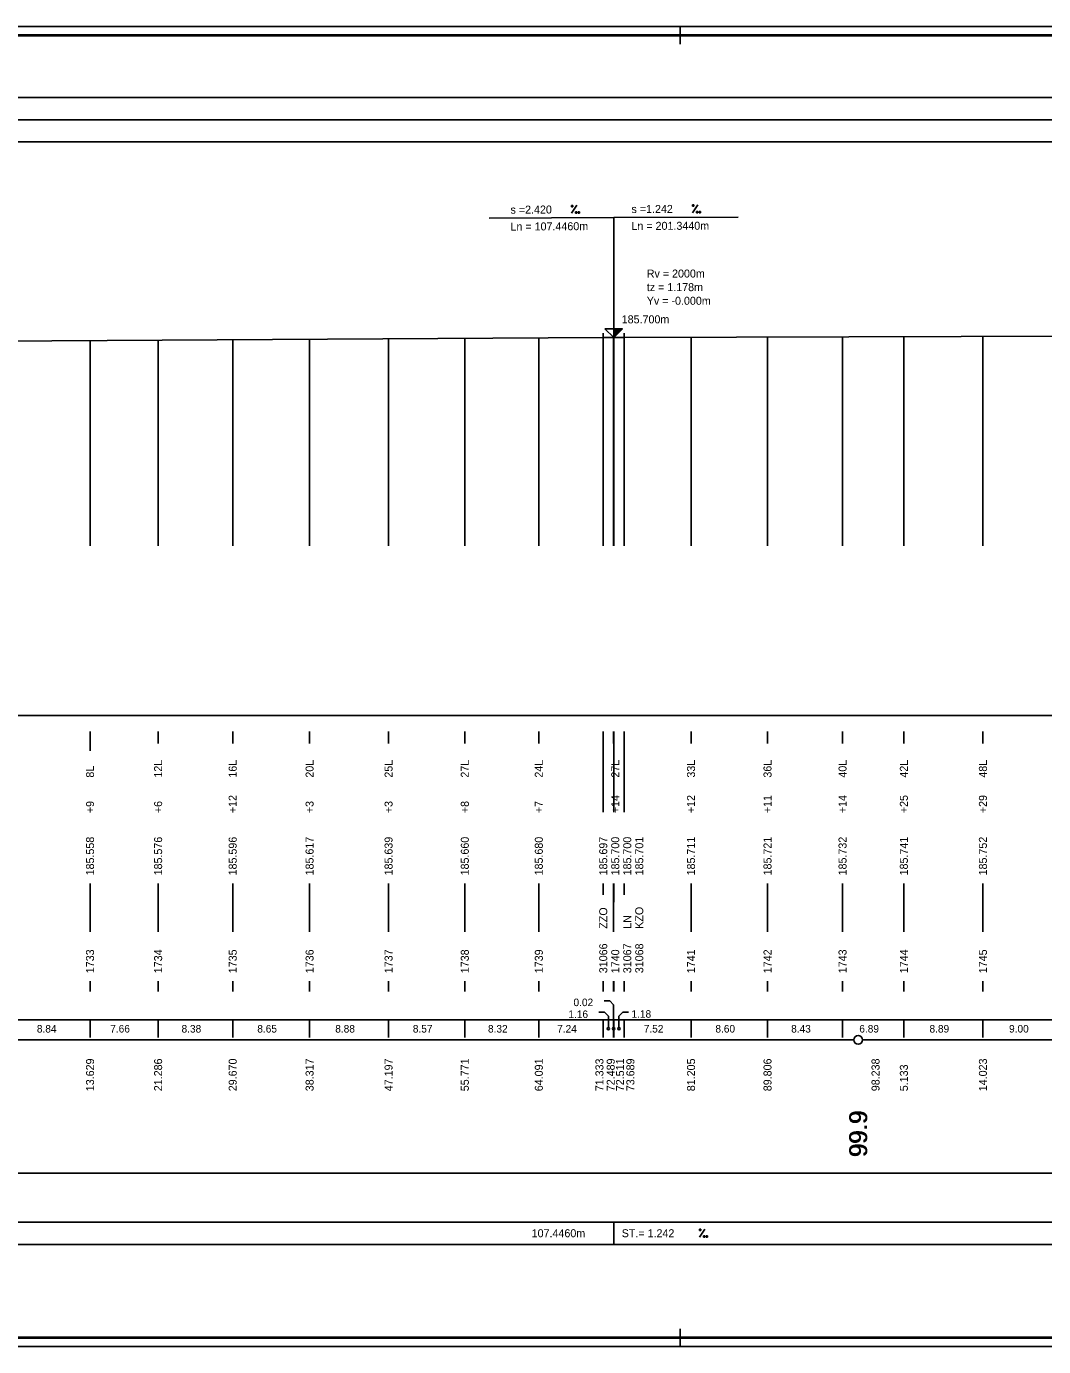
# Model space of a CAD drawing. Extents: x 0 to 10087, y -805 to 297.
# Drawn here: x 6993 to 7221.7, y 0 to 297 of the extents above; entities that cross this region are included whole.
import ezdxf

# ---------------------------------------------------------------- set-up
doc = ezdxf.new("R2010")
doc.units = 0
for name, color, linetype in [('CARKY_HODNOT', 7, 'Continuous'), ('KRIV1_CARA', 7, 'Continuous'), ('NIVELETA_CARA', 7, 'Continuous'), ('NIVELETA_TEXT', 7, 'Continuous'), ('PREV_CARA', 7, 'Continuous'), ('RAM', 7, 'Continuous'), ('REZERVA', 7, 'Continuous'), ('STAN_CARA', 7, 'Continuous'), ('STAN_PAS', 7, 'Continuous'), ('STAN_TEXT', 7, 'Continuous'), ('TEXT', 7, 'Continuous'), ('TXT_C_BODU', 7, 'Continuous')]:
    doc.layers.add(name, color=color, linetype=linetype)

msp = doc.modelspace()

# ---------------------------------------------------------------- linework, layer by layer
at = {"layer": 'CARKY_HODNOT'}
for p, q in [((7007.26, 180.14), (7007.26, 226.29)), ((7022.57, 180.14), (7022.57, 226.38)), ((7039.34, 180.14), (7039.34, 226.48)), ((7056.63, 180.14), (7056.63, 226.59)), ((7074.39, 180.14), (7074.39, 226.69)), ((7091.54, 180.14), (7091.54, 226.8)), ((7108.18, 180.14), (7108.18, 226.9)), ((7122.67, 180.14), (7122.67, 226.99)), ((7124.98, 180.14), (7124.98, 227)), ((7125.02, 180.14), (7125.02, 227)), ((7127.38, 180.14), (7127.38, 227.01)), ((7142.41, 180.14), (7142.41, 227.05)), ((7159.61, 180.14), (7159.61, 227.11)), ((7176.48, 180.14), (7176.48, 227.16)), ((7190.27, 180.14), (7190.27, 227.2)), ((7208.05, 180.14), (7208.05, 227.26)), ((7007.26, 134), (7007.26, 138.35)), ((7022.57, 135.65), (7022.57, 138.35)), ((7039.34, 135.65), (7039.34, 138.35)), ((7056.63, 135.65), (7056.63, 138.35)), ((7074.39, 135.65), (7074.39, 138.35)), ((7091.54, 135.65), (7091.54, 138.35)), ((7108.18, 135.65), (7108.18, 138.35)), ((7122.67, 126.2), (7122.67, 138.35)), ((7124.98, 135.65), (7124.98, 138.35)), ((7125.02, 126.2), (7125.02, 138.35)), ((7127.38, 126.2), (7127.38, 138.35)), ((7142.41, 135.65), (7142.41, 138.35)), ((7159.61, 135.65), (7159.61, 138.35)), ((7176.48, 135.65), (7176.48, 138.35)), ((7190.27, 135.65), (7190.27, 138.35)), ((7208.05, 135.65), (7208.05, 138.35)), ((7122.67, 120.25), (7122.67, 126.2)), ((7125.02, 120.25), (7125.02, 126.2)), ((7127.38, 120.25), (7127.38, 126.2)), ((7007.26, 93.3), (7007.26, 104.2)), ((7022.57, 93.3), (7022.57, 104.2)), ((7039.34, 93.3), (7039.34, 104.2)), ((7056.63, 93.3), (7056.63, 104.2)), ((7074.39, 93.3), (7074.39, 104.2)), ((7091.54, 93.3), (7091.54, 104.2)), ((7108.18, 93.3), (7108.18, 104.2)), ((7122.67, 101.65), (7122.67, 104.2)), ((7124.98, 93.3), (7124.98, 104.2)), ((7125.02, 100), (7125.02, 104.2)), ((7127.38, 101.65), (7127.38, 104.2)), ((7142.41, 93.3), (7142.41, 104.2)), ((7159.61, 93.3), (7159.61, 104.2)), ((7176.48, 93.3), (7176.48, 104.2)), ((7190.27, 93.3), (7190.27, 104.2)), ((7208.05, 93.3), (7208.05, 104.2)), ((7007.26, 79.9), (7007.26, 82.2)), ((7022.57, 79.9), (7022.57, 82.2)), ((7039.34, 79.9), (7039.34, 82.2)), ((7056.63, 79.9), (7056.63, 82.2)), ((7074.39, 79.9), (7074.39, 82.2)), ((7091.54, 79.9), (7091.54, 82.2)), ((7108.18, 79.9), (7108.18, 82.2)), ((7122.67, 79.9), (7122.67, 82.2)), ((7124.98, 79.9), (7124.98, 82.2)), ((7125.02, 79.9), (7125.02, 82.2)), ((7127.38, 79.9), (7127.38, 82.2)), ((7142.41, 79.9), (7142.41, 82.2)), ((7159.61, 79.9), (7159.61, 82.2)), ((7176.48, 79.9), (7176.48, 82.2)), ((7190.27, 79.9), (7190.27, 82.2)), ((7208.05, 79.9), (7208.05, 82.2))]:
    msp.add_line(p, q, dxfattribs=at)
at = {"layer": 'KRIV1_CARA'}
msp.add_line((6645.11, 39), (7238.99, 39), dxfattribs=at)
at = {"layer": 'NIVELETA_CARA'}
for p, q in [((300, 281), (8321.33, 281)), ((300, 276), (8321.33, 276)), ((300, 271), (8321.33, 271)), ((7125.02, 254), (7097.02, 253.83)), ((7125.02, 254), (7153.02, 254.09)), ((7125.02, 227), (7125.02, 254)), ((7125.02, 227), (7123.02, 229)), ((7123.02, 229), (7127.02, 229)), ((7125.02, 227), (7125.02, 229)), ((7127.02, 229), (7125.02, 227)), ((7125.09, 227.07), (7125.09, 229)), ((7125.16, 227.13), (7125.16, 229)), ((7125.22, 227.2), (7125.22, 229)), ((7125.29, 227.27), (7125.29, 229)), ((7125.36, 227.33), (7125.36, 229)), ((7125.42, 227.4), (7125.42, 229)), ((7125.49, 227.47), (7125.49, 229)), ((7125.56, 227.53), (7125.56, 229)), ((7125.62, 227.6), (7125.62, 229)), ((7125.69, 227.67), (7125.69, 229)), ((7125.76, 227.73), (7125.76, 229)), ((7125.82, 227.8), (7125.82, 229)), ((7125.89, 227.87), (7125.89, 229)), ((7125.96, 227.93), (7125.96, 229)), ((7126.02, 228), (7126.02, 229)), ((7126.09, 228.07), (7126.09, 229)), ((7126.16, 228.13), (7126.16, 229)), ((7126.22, 228.2), (7126.22, 229)), ((7126.29, 228.27), (7126.29, 229)), ((7126.36, 228.33), (7126.36, 229)), ((7126.42, 228.4), (7126.42, 229)), ((7126.49, 228.47), (7126.49, 229)), ((7126.56, 228.53), (7126.56, 229)), ((7126.62, 228.6), (7126.62, 229)), ((7126.69, 228.67), (7126.69, 229)), ((7126.76, 228.73), (7126.76, 229)), ((7126.82, 228.8), (7126.82, 229)), ((7126.89, 228.87), (7126.89, 229)), ((7126.96, 228.93), (7126.96, 229)), ((6911.02, 225.71), (7122.67, 226.99)), ((7122.67, 226.99), (7122.67, 227.99)), ((7122.67, 226.99), (7125.02, 227)), ((7122.67, 226.99), (7123.17, 226.99)), ((7123.17, 226.99), (7123.67, 226.99)), ((7123.67, 226.99), (7124.17, 226.99)), ((7124.17, 226.99), (7124.67, 227)), ((7124.67, 227), (7125.02, 227)), ((7125.02, 227), (7127.38, 227.01)), ((7125.02, 227), (7125.52, 227)), ((7125.52, 227), (7126.02, 227)), ((7126.02, 227), (7126.52, 227)), ((7126.52, 227), (7127.02, 227.01)), ((7127.02, 227.01), (7127.38, 227.01)), ((7127.38, 227.01), (7522.48, 228.23)), ((7127.38, 227.01), (7127.38, 228.01)), ((500, 28), (8321.33, 28)), ((7125.02, 23), (7125.02, 28)), ((500, 23), (8321.33, 23))]:
    msp.add_line(p, q, dxfattribs=at)
at = {"layer": 'NIVELETA_TEXT'}
for p, q in [((7115.51, 256.74), (7115.52, 256.44)), ((7115.52, 256.74), (7115.51, 256.73)), ((7115.52, 254.95), (7116.7, 256.75)), ((7115.81, 256.74), (7115.52, 256.74)), ((7115.52, 256.44), (7115.81, 256.44)), ((7115.81, 256.44), (7115.81, 256.74)), ((7142.72, 255.06), (7143.91, 256.86)), ((7142.72, 256.85), (7142.72, 256.55)), ((7143.02, 256.85), (7142.72, 256.85)), ((7142.72, 256.85), (7142.72, 256.85)), ((7142.72, 256.55), (7143.02, 256.56)), ((7143.02, 256.56), (7143.02, 256.85)), ((7116.43, 255.25), (7116.43, 254.95)), ((7116.44, 255.25), (7116.43, 255.24)), ((7116.43, 254.95), (7116.73, 254.95)), ((7116.73, 255.25), (7116.44, 255.25)), ((7116.73, 254.95), (7116.73, 255.25)), ((7117.04, 255.25), (7117.05, 254.95)), ((7117.05, 255.25), (7117.04, 255.25)), ((7117.34, 255.25), (7117.05, 255.25)), ((7117.05, 254.95), (7117.34, 254.96)), ((7117.34, 254.96), (7117.34, 255.25)), ((7143.63, 255.36), (7143.63, 255.06)), ((7143.64, 255.36), (7143.63, 255.35)), ((7143.63, 255.06), (7143.93, 255.06)), ((7143.93, 255.36), (7143.64, 255.36)), ((7143.93, 255.06), (7143.93, 255.36)), ((7144.25, 255.36), (7144.25, 255.06)), ((7144.54, 255.36), (7144.25, 255.36)), ((7144.25, 255.36), (7144.25, 255.35)), ((7144.25, 255.06), (7144.54, 255.06)), ((7144.54, 255.06), (7144.54, 255.36)), ((7144.32, 24.6), (7145.51, 26.4)), ((7144.32, 26.4), (7144.32, 26.1)), ((7144.33, 26.4), (7144.32, 26.39)), ((7144.32, 26.1), (7144.62, 26.1)), ((7144.62, 26.4), (7144.33, 26.4)), ((7144.62, 26.1), (7144.62, 26.4)), ((7145.23, 24.9), (7145.23, 24.6)), ((7145.24, 24.9), (7145.23, 24.89)), ((7145.23, 24.6), (7145.53, 24.6)), ((7145.53, 24.9), (7145.24, 24.9)), ((7145.53, 24.6), (7145.53, 24.9)), ((7145.85, 24.9), (7145.85, 24.6)), ((7146.14, 24.9), (7145.85, 24.9)), ((7145.85, 24.9), (7145.85, 24.89)), ((7145.85, 24.6), (7146.14, 24.6)), ((7146.14, 24.6), (7146.14, 24.9))]:
    msp.add_line(p, q, dxfattribs=at)
at = {"layer": 'PREV_CARA'}
msp.add_line((6645.11, 142), (7238.99, 142), dxfattribs=at)
at = {"layer": 'RAM'}
for p, q in [((8636.33, 297), (0, 297)), ((7140, 293), (7140, 297)), ((8634.33, 295.1), (2, 295.1)), ((8634.33, 295), (2, 295)), ((8634.33, 294.9), (2, 294.9)), ((7140, 0), (7140, 4)), ((0, 0), (8636.33, 0)), ((2, 2.1), (8634.33, 2.1)), ((2, 2), (8634.33, 2)), ((2, 1.9), (8634.33, 1.9))]:
    msp.add_line(p, q, dxfattribs=at)
at = {"layer": 'REZERVA'}
msp.add_circle((7180, 69), 1, dxfattribs=at)
at = {"layer": 'STAN_CARA'}
for p, q in [((6981, 69), (7179, 69)), ((7181, 69), (7378.5, 69))]:
    msp.add_line(p, q, dxfattribs=at)
at = {"layer": 'STAN_PAS'}
for p, q in [((7124.15, 77.75), (7122.88, 77.75)), ((7125, 76.9), (7124.15, 77.75)), ((7122.97, 75.2), (7121.7, 75.2)), ((7123.82, 74.35), (7122.97, 75.2)), ((7123.82, 71.75), (7123.82, 74.35)), ((7125, 71.75), (7125, 76.9)), ((7126.2, 74.35), (7127.05, 75.2)), ((7126.2, 71.75), (7126.2, 74.35)), ((7127.05, 75.2), (7128.33, 75.2)), ((300, 73.5), (8321.33, 73.5)), ((7007.26, 69.5), (7007.26, 73.5)), ((7022.57, 69.5), (7022.57, 73.5)), ((7039.34, 69.5), (7039.34, 73.5)), ((7056.63, 69.5), (7056.63, 73.5)), ((7074.39, 69.5), (7074.39, 73.5)), ((7091.54, 69.5), (7091.54, 73.5)), ((7108.18, 69.5), (7108.18, 73.5)), ((7122.67, 69.5), (7122.67, 73.5)), ((7124.98, 69.5), (7124.98, 73.5)), ((7125.02, 69.5), (7125.02, 73.5)), ((7127.38, 69.5), (7127.38, 73.5)), ((7142.41, 69.5), (7142.41, 73.5)), ((7159.61, 69.5), (7159.61, 73.5)), ((7176.48, 69.5), (7176.48, 73.5)), ((7190.27, 69.5), (7190.27, 73.5)), ((7208.05, 69.5), (7208.05, 73.5))]:
    msp.add_line(p, q, dxfattribs=at)
for centre in [(7123.82, 71.5), (7125, 71.5), (7126.2, 71.5)]:
    msp.add_circle(centre, 0.25, dxfattribs=at)

# ---------------------------------------------------------------- texts
at = {"layer": 'NIVELETA_TEXT'}
for s, rotation, p in [('s =2.420', 0.3466, (7101.82, 254.86)), ('s =1.242', 0.1779, (7129.02, 255.01)), ('Ln = 107.4460m', 0.3466, (7101.82, 251.06)), ('Ln = 201.3440m', 0.1779, (7129.02, 251.21))]:
    msp.add_text(s, height=1.8, rotation=rotation, dxfattribs=at).set_placement(p)
for s, p in [('Rv = 2000m', (7132.46, 240.5)), ('tz = 1.178m', (7132.46, 237.44)), ('Yv = -0.000m', (7132.46, 234.38)), ('185.700m', (7126.82, 230.2)), ('107.4460m', (7106.57, 24.6)), ('ST.= 1.242', (7126.82, 24.6))]:
    msp.add_text(s, height=1.8, dxfattribs=at).set_placement(p)
at = {"layer": 'STAN_TEXT'}
for s, p in [('0.02', (7115.98, 76.59)), ('1.16', (7114.83, 73.92)), ('1.18', (7129.02, 73.98)), ('8.84', (6995.3, 70.65)), ('7.66', (7011.8, 70.65)), ('8.38', (7027.84, 70.65)), ('8.65', (7044.87, 70.65)), ('8.88', (7062.4, 70.65)), ('8.57', (7079.85, 70.65)), ('8.32', (7096.75, 70.65)), ('7.24', (7112.31, 70.65)), ('7.52', (7131.78, 70.65)), ('8.60', (7147.89, 70.65)), ('8.43', (7164.93, 70.65)), ('6.89', (7180.25, 70.65)), ('8.89', (7196.04, 70.65)), ('9.00', (7213.93, 70.65))]:
    msp.add_text(s, height=1.7, dxfattribs=at).set_placement(p)
for s, height, p in [('13.629', 1.8, (7008.16, 57.45)), ('21.286', 1.8, (7023.47, 57.45)), ('29.670', 1.8, (7040.24, 57.45)), ('38.317', 1.8, (7057.53, 57.45)), ('47.197', 1.8, (7075.29, 57.45)), ('55.771', 1.8, (7092.44, 57.45)), ('64.091', 1.8, (7109.08, 57.45)), ('71.333', 1.8, (7122.71, 57.45)), ('72.489', 1.8, (7125.25, 57.45)), ('72.511', 1.8, (7127.34, 57.45)), ('73.689', 1.8, (7129.67, 57.45)), ('81.205', 1.8, (7143.31, 57.45)), ('89.806', 1.8, (7160.51, 57.45)), ('98.238', 1.8, (7184.8, 57.45)), ('5.133', 1.8, (7191.17, 57.45)), ('14.023', 1.8, (7208.95, 57.45)), ('    99.9', 4, (7182, 36.84)), ('    99.9', 4, (7182, 36.74)), ('    99.9', 4, (7182, 36.64))]:
    msp.add_text(s, height=height, rotation=90, dxfattribs=at).set_placement(p)
at = {"layer": 'TEXT'}
for s, p in [('12L', (7023.47, 128)), ('16L', (7040.24, 128)), ('20L', (7057.53, 128)), ('25L', (7075.29, 128)), ('27L', (7092.44, 128)), ('24L', (7109.08, 128)), ('27L', (7126.27, 128)), ('33L', (7143.31, 128)), ('36L', (7160.51, 128)), ('40L', (7177.38, 128)), ('42L', (7191.17, 128)), ('48L', (7208.95, 128)), ('8L', (7008.16, 128)), ('+9', (7008.16, 120)), ('+6', (7023.47, 120)), ('+12', (7040.24, 120)), ('+3', (7057.53, 120)), ('+3', (7075.29, 120)), ('+8', (7092.44, 120)), ('+7', (7109.08, 120)), ('+14', (7126.27, 120)), ('+12', (7143.31, 120)), ('+11', (7160.51, 120)), ('+14', (7177.38, 120)), ('+25', (7191.17, 120)), ('+29', (7208.95, 120)), ('185.558', (7008.16, 106)), ('185.576', (7023.47, 106)), ('185.596', (7040.24, 106)), ('185.617', (7057.53, 106)), ('185.639', (7075.29, 106)), ('185.660', (7092.44, 106)), ('185.680', (7109.08, 106)), ('185.697', (7123.57, 106)), ('185.700', (7126.27, 106)), ('185.700', (7128.97, 106)), ('185.701', (7131.67, 106)), ('185.711', (7143.31, 106)), ('185.721', (7160.51, 106)), ('185.732', (7177.38, 106)), ('185.741', (7191.17, 106)), ('185.752', (7208.95, 106)), ('ZZO', (7123.57, 94)), ('KZO', (7131.67, 94)), ('LN', (7128.97, 94))]:
    msp.add_text(s, height=1.8, rotation=90, dxfattribs=at).set_placement(p)
at = {"layer": 'TXT_C_BODU'}
for s, p in [('1733', (7008.16, 84)), ('1734', (7023.47, 84)), ('1735', (7040.24, 84)), ('1736', (7057.53, 84)), ('1737', (7075.29, 84)), ('1738', (7092.44, 84)), ('1739', (7109.08, 84)), ('31066', (7123.57, 84)), ('1740', (7126.27, 84)), ('31067', (7128.97, 84)), ('31068', (7131.67, 84)), ('1741', (7143.31, 84)), ('1742', (7160.51, 84)), ('1743', (7177.38, 84)), ('1744', (7191.17, 84)), ('1745', (7208.95, 84))]:
    msp.add_text(s, height=1.8, rotation=90, dxfattribs=at).set_placement(p)

doc.saveas('drawing.dxf')
